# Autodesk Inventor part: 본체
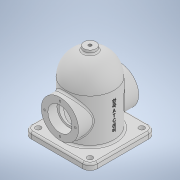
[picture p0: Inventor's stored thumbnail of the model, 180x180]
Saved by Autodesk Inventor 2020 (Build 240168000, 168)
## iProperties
Created: 2021-07
Part Number: 본체
Material: 일반
Document SubType Name: Modeling
Designer: Owner
Density: 1 g/cm^3
Appearance: 기본값
Author: Owner
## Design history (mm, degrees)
sketch "스케치1"
  geometry: C1 r 40 at (0, 0); 1 further point
  constraints: 1 centre point, 1 coincident
  dimensions: "d0" = 80 diameter of C1
extrude "돌출1" new body sketch "스케치1" distance "d1" = 124; taper "d2" = 0 deg
fillet "모깎기1" dims "d3" = 40
feature "쉘1" dims "d4" = 8
node "작업 평면1"
sketch "스케치2"
  geometry: C1 r 31 at (0, 48); 1 further point
  constraints: 1 centre point, 1 vertical alignment
  dimensions: "d6" = 62 diameter of C1; "d7" = 48 distance of point (0, 0) C1.centre
extrude "돌출2" join sketch "스케치2" stored distance "d8" = 124; taper "d9" = 0 deg
sketch "스케치3"
  geometry: C1 r 31 at (0, 0) reference; 2 further points
  constraints: 1 coincident
hole "구멍1" sketch "스케치3" at (0, 0) diameter "d10" = 33; stored, may be unused: countersink angle "d14" = 90 deg, drill point angle "d16" = 118 deg; dims "d11" = 6, "d12" = 40, "d13" = 15, "d15" = 49.25
sketch "스케치4"
  geometry: C1 r 16.5 at (0, 0) reference; 2 further points
  constraints: 1 vertical alignment
  dimensions: "d17" = 25.5 distance of C1.centre point (0, 25.5)
hole "구멍2" sketch "스케치4" at (0, 25.5) diameter "d18" = 3.242; stored, may be unused: countersink angle "d22" = 90 deg, drill point angle "d24" = 118 deg; dims "d19" = 8, "d20" = 40, "d21" = 15, "d23" = 10
sketch "스케치5"
  geometry: L1 (-55, 55)-(55, 55); L2 (55, 55)-(55, -55); L3 (55, -55)-(-55, -55); L4 (-55, -55)-(-55, 55); L5 (-55, 55)-(55, -55); L6 (55, 55)-(-55, -55); C1 r 40 at (0, 0) reference; 1 further point
  constraints: 12 end point, 2 midpoint, 2 parallel, 1 horizontal, 1 perpendicular
  dimensions: "d28" = 110 distance of L2.end L3.end; "d29" = 110 distance of L1.end L2.end
extrude "돌출3" join sketch "스케치5" distance "d30" = 10; taper "d31" = 0 deg
fillet "모깎기2" dims "d32" = 12
fillet "모깎기3" dims "d33" = 3
fillet "모깎기4" dims "d34" = 3
node "작업 평면2"
sketch "스케치6"
  geometry: C1 r 10 at (0, 0); 1 further point
  constraints: 1 centre point, 1 coincident
  dimensions: "d36" = 20 diameter of C1
extrude "돌출4" join sketch "스케치6" stored distance "d37" = 10; taper "d38" = 0 deg
sketch "스케치7"
  geometry: C1 r 10 at (0, 0) reference; 2 further points
  constraints: 1 coincident
hole "구멍3" sketch "스케치7" at (0, 0) diameter "d39" = 5.1881; stored, may be unused: countersink angle "d43" = 90 deg, drill point angle "d45" = 118 deg; dims "d40" = 29.25, "d41" = 40, "d42" = 15, "d44" = 36
fillet "모깎기5" dims "d46" = 3
sketch "스케치8"
  geometry: A1 r 9 centre (-43, -43) between (-52, -43) and (-43, -52) reference; 2 further points
  constraints: 1 coincident
hole "구멍4" sketch "스케치8" at (-43, -43) diameter "d47" = 9; stored, may be unused: countersink angle "d51" = 90 deg, drill point angle "d53" = 118 deg; dims "d48" = 29.25, "d49" = 40, "d50" = 15, "d52" = 36
node "작업 평면3"
sketch "스케치9"
  geometry: L1 (0, -43)-(0, 43) reference; 2 further points
  constraints: 1 horizontal alignment, 1 other
  dimensions: "d58" = 48 distance from line of L1 point (48, 0)
feature "엠보싱1" sketch "스케치9" dims "d59" = 0.5, "d60" = 0
node "솔리드1"
mirror "미러1"
pattern_circular "원형 패턴1" dims angle "d26" = 360 deg
mirror "미러2"
pattern_circular "원형 패턴2" dims angle "d55" = 360 deg
feature "A9D066F2-1C7D-4E18-AEED-F7BC21143FA4" dims "d10" = 33, "d11" = 6, "d12" = 40, "d13" = 15, "d14" = 90 deg, "d15" = 49.25, "d16" = 118 deg
other parameters: "d35" = -129
